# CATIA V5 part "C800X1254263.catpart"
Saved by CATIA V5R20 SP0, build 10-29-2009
Part number: C800X1254263
Source: Unknown
Property "A": "50"
Property "ARTICLENO": "C800X1254263"
Property "B": "23"
Property "BOMINFO": "C800X1254263"
Property "C": "91"
Property "CA": "C800X1254263"
Property "D1": "90"
Property "DES": "ROTATING EYEBOLT WITH RING Ton 12,5 M42x63"
Property "E": "86"
Property "H": "200"
Property "L": "63"
Property "LINA": "C800X1254263"
Property "NB": "C800X1254263"
Property "NBSYN": "$CODE."
Property "NN": "C800X"
Property "NT": "Rotating eyebolt with ring"
Property "SIZE": "M42"
Property "SUPPLIER": "CF"
Property "SW": "80"
Property "WEIGHT": "5200"
Property "WLL": "12.50"
Bounding box of the stored display mesh (mm): x -47.825 to 48, y -63 to 222.825, z -45 to 45
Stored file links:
  C:\Users\Utente\Desktop\3D files 800X\C800X1254263.catpart

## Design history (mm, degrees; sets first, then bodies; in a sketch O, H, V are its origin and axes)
Body1 "Geometry.1" (main body)
  Solid1 "C800X1254263.catpart": solid without history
